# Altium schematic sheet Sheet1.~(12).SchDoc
size A4; SheetNumber: 1; SheetTotal: 1
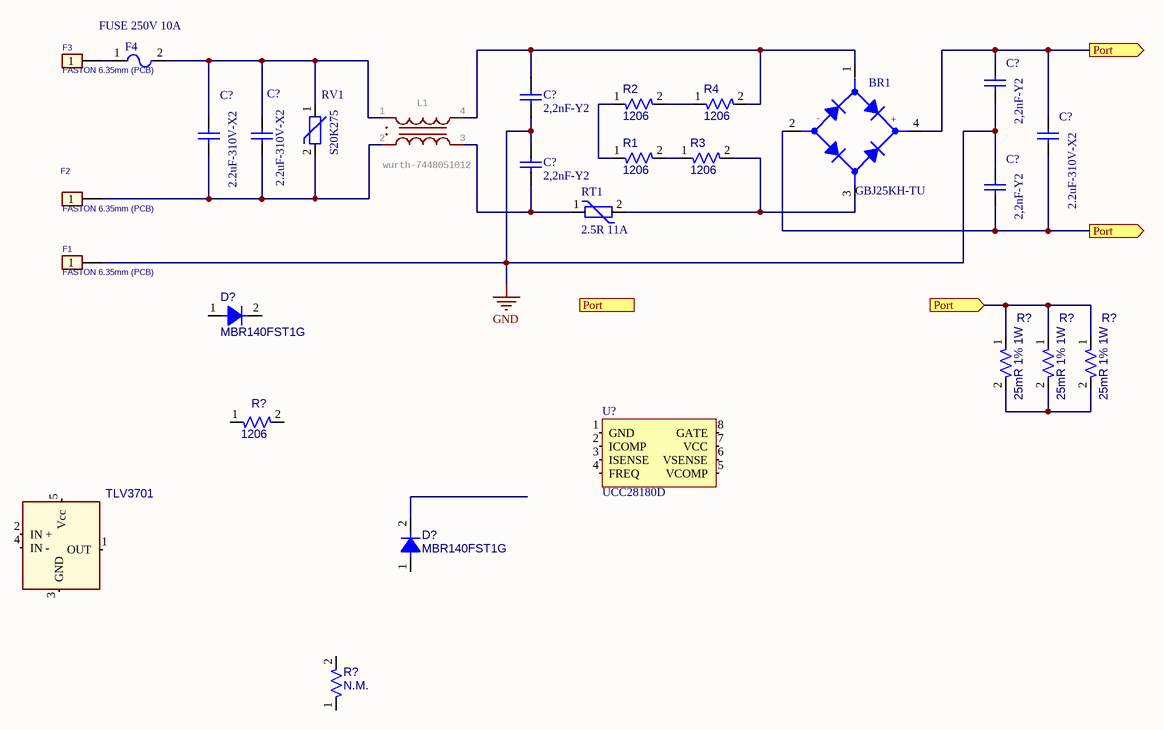
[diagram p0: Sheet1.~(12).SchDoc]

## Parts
(Parts that share a designator on the sheet are numbered #1, #2 ... from top to bottom, then left to right.)
BR1  GBJ25KH-TU
C?#1  2,2nF-Y2
C?#2  2,2nF-Y2
C?#3  2.2uF-310V-X2
C?#4  2.2uF-310V-X2
C?#5  2.2uF-310V-X2
C?#6  2,2nF-Y2
C?#7  2,2nF-Y2
D?#1  MBR140FST1G
D?#2  MBR140FST1G
F1  FASTON 6.35mm (PCB)  [FASTON_M_PCB_6.35x0.81]
F2  FASTON 6.35mm (PCB)  [FASTON_M_PCB_6.35x0.81]
F3  FASTON 6.35mm (PCB)  [FASTON_M_PCB_6.35x0.81]
F4  FUSE 250V 10A
L1  wurth-7448051012  [WE-CMBNC_XL_7448051012]
R1  1206  [1206_UP_RES]
R2  1206  [1206_UP_RES]
R3  1206  [1206_UP_RES]
R4  1206  [1206_UP_RES]
R?#1  25mR 1% 1W  [2512_up]
R?#2  25mR 1% 1W  [2512_up]
R?#3  25mR 1% 1W  [2512_up]
R?#4  1206  [1206_UP_RES]
R?#5  N.M.  [0603N_RES]
RT1  2.5R 11A
RV1  S20K275
TLV3701  TLV3701 SOT23-5L  [SOT-23 5PIN]  (value not drawn)
U?  UCC28180D  [SO8]

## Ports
Port (in), Port (out)

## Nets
GND: C?#1.1 C?#2.1 C?#6.2 C?#7.2 F1.1
Port: BR1.2(-DC) BR1.4(+DC) C?#1.2 C?#5.1 C?#5.2 C?#7.1 R?#1.1 R?#2.1 R?#3.1 ; port Port
NetBR1_1: BR1.1(AC1) C?#2.2 L1.4 R4.2
NetBR1_3: BR1.3(AC2) R3.2 RT1.2
NetC?#3_1: C?#3.1 C?#4.1 F4.2 L1.1 RV1.1
NetC?#3_2: C?#3.2 C?#4.2 F2.1 L1.2 RV1.2
NetC?#6_1: C?#6.1 L1.3 RT1.1
NetF3_1: F3.1 F4.1
NetR1_1: R1.1 R2.1
NetR1_2: R1.2 R3.1
NetR2_2: R2.2 R4.1
NetR?#1_2: R?#1.2 R?#2.2 R?#3.2

Not connected (* = marked no-connect by the designer): D?#1 1 2; D?#2 1 2; R?#4 1 2; R?#5 1 2; TLV3701 1(OUT) 2(IN_+) 3(GND) 4(IN_-) 5(Vcc); U? 1(GND) 2(ICOMP) 3(ISENSE) 4(FREQ) 5(VCOMP) 6(VSENSE) 7(VCC) 8(GATE)

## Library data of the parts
BR1 = BRIDGE_D15XB60_15A_600V: BRIDGE DIOTEC GBJ25KH-TU 25A 800V; Costo: 0; Aggiornato: NO
C?#1 C?#2 C?#6 C?#7 = Cap: 2,2nF-Y2-300V MURATA DE6E3KJ222MA4B; Value: 2,2nF
C?#3-C?#5 = Cap: 2.2uF-310V-X2  VISHAY F339M/52231MIM2T0; Value: 2,2uF
D?#1 D?#2 = D_LL4148: ON SEMICUNDUCTOR, Schottky Power Rectifier, 1.0 A, 40 V, SOD-123FL; Aggiornato: SI; ContoLavoro: 0
F1-F3 = FASTON_M_PCB_6.35mm: FASTON M PCB 6.35mm; Hpcode: FASTMASCSTAMP; Costo: 0,01; Aggiornato: s; ContoLavoro: 0
F4 = FUSE_250V_6.3A_T_BEL_FUSE_0697A6300-01: PORTAFUIBILE DA C.S.  250Vac 10A 6,3x32; Aggiornato: S; ContoLavoro: 0
L1 = WE-CMBNC_XL_7448051012: GateName_1: G$1; IR: 10A; RDC: 15mOhm; VR: 250  V (AC); VT: 1500  V (AC)
R1-R4 R?#4 = R_0.33_1%_1206: 1206 SMD RESISTOR; Aggiornato: s; ContoLavoro: 0
R?#1-R?#3 = R_0.5R_1%_2512: 25mOhm 1% 2512 1W WSL SMD RESISTOR; Costo: 0,40; Value: 0,025; Aggiornato: s; ContoLavoro: 0
R?#5 = R_0R_1%_0603: 0R 1% 0603 SMD RESISTOR; Costo: 0,00073; Value: 0; Aggiornato: S
RT1 = RT_2.5R_10A: NTC 2.5R 11A  TDK B57364S0259M0 21x7; Costo: 0; Aggiornato: NO
RV1 = VARISTOR: VARISTORE TDK S20K275 B72220S0271K101; Aggiornato: NO; ContoLavoro: 0
TLV3701 = TLV3701 SOT23-5L: Costo: 0; DeviceFunction: Voltage Regulator; Aggiornato: NO
U? = UCC28180D: Costo: 1,534; Aggiornato: NO; ContoLavoro: 0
